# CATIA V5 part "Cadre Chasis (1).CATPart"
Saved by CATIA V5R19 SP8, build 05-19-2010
Part number: Cadre Chasis (1)
Nomenclature: 1
Material "Acier": density 7860 kg/m3, Young's modulus 2e+11 Pa, Poisson ratio 0.266, thermal expansion 1.17e-05 1/K
Bounding box of the stored display mesh (mm): x -290 to 290, y 0 to 780, z -38 to 20
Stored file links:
  C:\Users\rphgr\Desktop\0_Tapis_TC520B_vitesse\Cadre Chasis (1).CATPart
  C:\Program Files (x86)\Dassault Systemes\B19\intel_a\reffiles\standard\MetricThickPitch.txt
  D:\Programmes\DassaultSysteme\win_b64\startup\materials\French\Catalog.CATMaterial
  D:\Documents\1_Travail\1 - ac-limoges.fr\ac-limoges.fr\Emmanuel Maynard - STI2D_Turgot\3 - Supports\Tapis de course TC520B\Tapis de course TC520B_Ca\0_Tapis_TC520B.CATProduct
  C:\Users\rphgr\Desktop\0_Tapis_TC520B_vitesse\Patin (54).CATPart
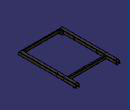
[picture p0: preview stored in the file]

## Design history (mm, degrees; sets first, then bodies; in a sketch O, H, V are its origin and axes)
AxisSystem1: origin (0, 0, 0), X (1, 0, 0), Y (0, 1, 0), Z (0, 0, 1)
Set1
  DatumSurface1: linked copy from another document
Set2
  Sketch1 on YZ plane of AxisSystem1, origin (0, 0, 0), H (0, 1, 0), V (0, 0, 1)
    line L1 (-54.6095, -38) -> (1600.6954, -38)
    reference intersected line E1 through (0, -38) direction (1, 0) from face of DatumSurface1
    coincidence: L1 E1
Body1 "Tube logitudinal" (main body)
  Sketch2 on zx-plane, origin (0, 0, 0), H (1, 0, 0), V (0, 0, -1)
    point P1 (-270, 0)
    line L1 (-250, 17) -> (-250, -17)
    line L2 (-253, -20) -> (-287, -20)
    line L3 (-290, -17) -> (-290, 17)
    line L4 (-287, 20) -> (-253, 20)
    arc A1 centre (-287, 17) radius 3 from (-290, 17) to (-287, 20) cw
    arc A2 centre (-253, 17) radius 3 from (-250, 17) to (-253, 20) ccw
    arc A3 centre (-253, -17) radius 3 from (-250, -17) to (-253, -20) cw
    arc A4 centre (-287, -17) radius 3 from (-287, -20) to (-290, -17) cw
    distance P1 V = 270
    radius A1 = 3
    radius A2 = 3
    radius A3 = 3
    radius A4 = 3
    distance L3 L1 = 40
    distance L4 L2 = 40
    coincidence: P1 H
    vertical: L1 V, L3 V
    horizontal: L2 H, L4 H
    equidistance: L1 L3 P1, L2 L4 P1
    tangency: A1 L3, A1 L4, A2 L1, A2 L4, A3 L1, A3 L2, A4 L2, A4 L3
  Pad1: profile Sketch2, direction (0, 1, 0), length 780, thin wall 1.7
  Sketch3 on face of Pad1, origin (-250, 0, 0), H (0, 1, 0), V (0, 0, 1)
    line L1 (0, -20) -> (10.718, 20)
    point P1 (0, -20)
    reference intersected line E1 (0, -20) -> (0, 20) from start face of Pad1
    line L2 (780, -20) -> (769.282, 20)
    point P3 (780, -20)
    reference intersected line E2 (780, 20) -> (780, -20) from end face of Pad1
    line L3 (10.718, 20) -> (769.282, 20)
    line L4 (780, -20) -> (0, -20)
    reference intersected line E3 through (0, 20) direction (1, 0) from face of Pad1
    reference intersected line E4 through (0, -20) direction (-1, 0) from face of Pad1
    reference intersected line E5 (0, -17) -> (0, 17) from start face of Pad1
    reference intersected line E6 (780, 17) -> (780, -17) from end face of Pad1
    angle L1 E1 = 15
    angle E2 L2 = 15
    horizontal: L3 H, L4 H
    coincidence: L3 E3, L4 E4, P1 E5, P3 E6
  Pocket1: profile Sketch3, direction (-1, 0, 0), through (limit type 3), outer side
  Sketch4 on face of Pad1, origin (0, 0, -20), H (1, 0, 0), V (0, -1, 0)
    point P1 (-270, -780)
    line L1 (-256.6806, -745) -> (-256.6806, -818)
    line L2 (-256.6806, -818) -> (-283.3194, -818)
    line L3 (-283.3194, -818) -> (-283.3194, -745)
    line L4 (-280.3194, -742) -> (-259.6806, -742)
    reference projected line E1 (-250, -780) -> (-290, -780) from edge [face of Pad1 | face of Pocket1 from Sketch3.L2]
    reference projected line E2 (-250, -780) -> (-290, -780) from edge [face of Pad1 | face of Pocket1 from Sketch3.L2]
    arc A1 centre (-280.3194, -745) radius 3 from (-283.3194, -745) to (-280.3194, -742) cw
    arc A2 centre (-259.6806, -745) radius 3 from (-256.6806, -745) to (-259.6806, -742) ccw
    reference intersected line E3 through (-250, 0) direction (0, -1) from face of Pad1
    length L2 = 26.6389
    distance L4 E2 = 38
    radius A1 = 3
    radius A2 = 3
    distance P1 E3 = 20
    vertical: L1 V, L3 V
    horizontal: L2 H, L4 H
    equidistance: L1 L3 P1, L2 L4 P1
    coincidence: P1 E1
    tangency: A1 L3, A1 L4, A2 L1, A2 L4
  Pocket2: profile Sketch4, direction (0, 0, 1), up to face of Pad1
  Sketch5 on face of Pad1, origin (0, 0, 20), H (1, 0, 0), V (0, 1, 0)
    point P1 (-270, 769.282)
    line L1 (-256.6806, 788.282) -> (-256.6806, 753.282)
    line L2 (-259.6806, 750.282) -> (-280.3194, 750.282)
    line L3 (-283.3194, 753.282) -> (-283.3194, 788.282)
    line L4 (-283.3194, 788.282) -> (-256.6806, 788.282)
    reference intersected line E1 through (-283.3194, 0) direction (0, -1) from face of Pocket2 from Sketch4.L3
    reference intersected line E2 through (-256.6806, 0) direction (0, 1) from face of Pocket2 from Sketch4.L1
    reference intersected line E3 (-253, 769.282) -> (-287, 769.282) from face of Pocket1 from Sketch3.L2
    reference intersected line E4 (-253, 769.282) -> (-287, 769.282) from face of Pocket1 from Sketch3.L2
    arc A1 centre (-280.3194, 753.282) radius 3 from (-280.3194, 750.282) to (-283.3194, 753.282) cw
    arc A2 centre (-259.6806, 753.282) radius 3 from (-256.6806, 753.282) to (-259.6806, 750.282) cw
    distance L2 E4 = 19
    radius A1 = 3
    radius A2 = 3
    vertical: L1 V, L3 V
    horizontal: L2 H, L4 H
    equidistance: L1 L3 P1, L2 L4 P1
    coincidence: L3 E1, L1 E2, P1 E3
    tangency: A1 L2, A1 L3, A2 L1, A2 L2
  Pocket3: profile Sketch5, direction (0, 0, -1), through (limit type 3)
  Sketch6 on face of Pad1, origin (-250, 0, 0), H (0, 1, 0), V (0, 0, 1)
    circle A1 centre (767, -4) radius 4.2
    point P1 (767, -4)
    reference intersected line E1 through (0, -20) direction (-1, 0) from face of Pad1
    reference projected point E2 (780, -20) from edge [face of Pad1 | face of Pocket1 from Sketch3.L2]
    circle A2 centre (607, -4) radius 4.2
    point P2 (607, -4)
    circle A3 centre (507, -4) radius 4.2
    point P3 (507, -4)
    reference intersected line E3 through (0, -20) direction (-1, 0) from face of Pad1
    reference intersected line E4 through (0, -20) direction (-1, 0) from face of Pad1
    radius A1 = 4.2
    distance P1 E1 = 16
    distance P1 E2 H = 13
    radius A3 = 4.2
    radius A2 = 4.2
    distance P2 E3 = 16
    distance P3 E4 = 16
    distance P2 P3 = 100
    distance P2 P1 = 160
  Pocket4: profile Sketch6, direction (-1, 0, 0), through (limit type 3)
  Sketch7 on face of Pad1, origin (-270.9117, 715.1257, -20), H (1, 0, 0), V (0, -1, 0)
    point P1 (0.9117, -14.8743)
    reference intersected line E1 through (20.9117, 0) direction (0, -1) from face of Pad1
    reference projected line E2 (17.9117, -64.8743) -> (-16.0883, -64.8743) from edge [face of Pad1 | face of Pocket1 from Sketch3.L2]
    distance P1 E1 = 20
    distance P1 E2 = 50
  Hole1: placed by Sketch7, at (-270, 730, -20) direction (0, 0, 1), diameter 6.647, depth 2, threaded "M8", thread diameter 8, thread depth 2, pitch 1.25
  Sketch8 on face of Pad1, origin (-269.3296, 31.4158, -20), H (1, 0, 0), V (0, -1, 0)
    point P1 (0, -8.5842)
    reference intersected line E1 through (-20.6704, 0) direction (0, 1) from face of Pad1
    reference projected line E2 (16.3296, 31.4158) -> (-17.6704, 31.4158) from edge [face of Pocket1 from Sketch3.L1 | face of Pad1]
    distance P1 E1 = 20.6704
    distance P1 E2 = 40
  Hole2: placed by Sketch8, at (-269.3296, 40, -20) direction (0, 0, 1), diameter 6.647, depth 20, threaded "M8", thread diameter 8, thread depth 2, pitch 1.25
  Sketch9 on face of Pad1, origin (-269.147, 626.9469, 20), H (1, 0, 0), V (0, 1, 0)
    point P1 (-6.853, -27.6649)
    reference projected line E1 (16.147, 142.3351) -> (-17.853, 142.3351) from edge [face of Pocket1 from Sketch3.L2 | face of Pad1]
    reference intersected line E2 through (-20.853, 0) direction (0, 1) from face of Pad1
    distance E1 P1 = 170
    distance P1 E2 = 14
  Hole3: placed by Sketch9, at (-276, 599.282, 20) direction (0, 0, -1), diameter 6.647, depth 20, threaded "M8", thread diameter 8, thread depth 2, pitch 1.25
  Sketch10 on face of Pad1, origin (-261.6012, 536.6172, 20), H (1, 0, 0), V (0, 1, 0)
    point P1 (-14.3988, -22.3352)
    reference projected point E1 (-14.3988, 62.6648) from axis of face of Hole3
    reference intersected line E2 through (-28.3988, 0) direction (0, 1) from face of Pad1
    distance P1 E1 = 85
    distance P1 E2 = 14
  Hole4: placed by Sketch10, at (-276, 514.282, 20) direction (0, 0, -1), diameter 6.647, depth 20, threaded "M8", thread diameter 8, thread depth 2, pitch 1.25
  Mirror1: of the body so far, about yz-plane
  Sketch11 on face of Pad1, origin (-290, 0, 0), H (0, -1, 0), V (0, 0, 1)
    construction line L1 (-552, 0) -> (-562, 0)
    point P1 (-552, 0)
    line L2 (-552, -11.5034) -> (-562, -11.5034)
    line L3 (-562, 11.5034) -> (-552, 11.5034)
    arc A1 centre (-562, 0) radius 11.5034 from (-562, -11.5034) to (-562, 11.5034) cw
    arc A2 centre (-552, 0) radius 11.5034 from (-552, 11.5034) to (-552, -11.5034) cw
    reference projected point E1 (-507, -4) from axis of face of Pocket4 from Sketch6.A3
    distance L1 L2 = 11.5034
    length L1 = 10
    distance E1 P1 H = 45
    coincidence: P1 H
    horizontal: L1 H
    tangency: A1 L2, A2 L2, A1 L3, A2 L3
  Pocket5: profile Sketch11, direction (1, 0, 0), length 2
  Sketch12 on face of Pad1, origin (-250, 0, 0), H (0, 1, 0), V (0, 0, 1)
    construction line L1 (200, 0) -> (210.54, 0)
    point P1 (200, 0)
    line L2 (200, 5.5) -> (210.54, 5.5)
    line L3 (210.54, -5.5) -> (200, -5.5)
    arc A1 centre (210.54, 0) radius 5.5 from (210.54, 5.5) to (210.54, -5.5) cw
    arc A2 centre (200, 0) radius 5.5 from (200, -5.5) to (200, 5.5) cw
    reference projected point E1 (0, -20) from edge [face of Pocket1 from Sketch3.L1 | face of Pad1]
    distance L1 L2 = 5.5
    length L1 = 10.54
    distance P1 E1 H = 200
    coincidence: P1 H
    horizontal: L1 H
    tangency: A1 L2, A2 L2, A1 L3, A2 L3
  Pocket6: profile Sketch12, direction (-1, 0, 0), length 2
Body2 "Traverses"
  Sketch13 on yz-plane, origin (0, 0, 0), H (0, 1, 0), V (0, 0, 1)
    point P1 (17.218, 0)
    line L1 (23.718, 17) -> (23.718, -17)
    line L2 (20.718, -20) -> (13.718, -20)
    line L3 (10.718, -17) -> (10.718, 17)
    line L4 (13.718, 20) -> (20.718, 20)
    reference intersected line E1 through (0, 20) direction (1, 0) from face of Mirror1
    reference projected point E2 (10.718, 20) from edge [face of Pad1 | face of Pocket1 from Sketch3.L1]
    arc A1 centre (20.718, 17) radius 3 from (23.718, 17) to (20.718, 20) ccw
    arc A2 centre (13.718, 17) radius 3 from (10.718, 17) to (13.718, 20) cw
    arc A3 centre (13.718, -17) radius 3 from (13.718, -20) to (10.718, -17) cw
    arc A4 centre (20.718, -17) radius 3 from (20.718, -20) to (23.718, -17) ccw
    radius A1 = 3
    radius A2 = 3
    radius A3 = 3
    radius A4 = 3
    distance L3 L1 = 13
    coincidence: P1 H, L4 E1, L3 E2
    vertical: L1 V, L3 V
    horizontal: L2 H, L4 H
    equidistance: L1 L3 P1, L2 L4 P1
    tangency: A1 L1, A1 L4, A2 L3, A2 L4, A3 L2, A3 L3, A4 L2, A4 L1
  Pad2: profile Sketch13, direction (1, 0, 0), up to face of Mirror1, opposite side up to face of Pad1, thin wall 1.7
  Sketch14 on yz-plane, origin (0, 0, 0), H (0, 1, 0), V (0, 0, 1)
    point P1 (625.968, 0)
    line L1 (636.218, 17) -> (636.218, -17)
    line L2 (633.218, -20) -> (618.718, -20)
    line L3 (615.718, -17) -> (615.718, 17)
    line L4 (618.718, 20) -> (633.218, 20)
    reference intersected line E1 through (0, 20) direction (1, 0) from face of Pad1
    reference intersected line E2 (23.718, 20) -> (23.718, -20) from face of Pad2
    arc A1 centre (618.718, 17) radius 3 from (615.718, 17) to (618.718, 20) cw
    arc A2 centre (633.218, 17) radius 3 from (636.218, 17) to (633.218, 20) ccw
    arc A3 centre (633.218, -17) radius 3 from (636.218, -17) to (633.218, -20) cw
    arc A4 centre (618.718, -17) radius 3 from (618.718, -20) to (615.718, -17) cw
    distance L3 L1 = 20.5
    distance L3 E2 = 592
    radius A1 = 3
    radius A2 = 3
    radius A3 = 3
    radius A4 = 3
    coincidence: P1 H, L4 E1
    vertical: L1 V, L3 V
    horizontal: L2 H, L4 H
    equidistance: L1 L3 P1, L2 L4 P1
    tangency: A1 L3, A1 L4, A2 L1, A2 L4, A3 L1, A3 L2, A4 L2, A4 L3
  Pad3: profile Sketch14, direction (1, 0, 0), up to face of Mirror1, opposite side up to face of Pad1, thin wall 1.7
Body3 "renfort d'angle"
  Sketch15 on face of Pad1, origin (0, 0, -20), H (1, 0, 0), V (0, -1, 0)
    point P1 (-250, -63.718)
    line L1 (-250, -63.718) -> (-239.5, -63.718)
    arc A1 centre (-239.5, -56.218) radius 7.5 from (-239.5, -63.718) to (-232, -56.218) ccw
    line L2 (-232, -56.218) -> (-232, -23.718)
    point P5 (-232, -23.718)
    reference intersected line E1 through (-250, 0) direction (0, -1) from face of Pad1
    reference intersected line E2 through (-250, 0) direction (0, -1) from face of Pad1
    reference intersected line E3 through (0, -23.718) direction (-1, 0) from face of Pad2
    reference intersected line E4 through (0, -23.718) direction (-1, 0) from face of Pad2
    radius A1 = 7.5
    distance L2 E2 = 18
    distance L1 E3 = 40
    horizontal: L1 H
    tangency: A1 L1, L2 A1
    coincidence: P1 E1, E4 P5
  Pad4: profile Sketch15, direction (0, 0, -1), up to face of Pad2, thin wall 0, second thickness 4
  Sketch16 on face of Pad4, origin (-228, 0, 0), H (0, 1, 0), V (0, 0, 1)
    circle A1 centre (48.718, -2) radius 6.25
    point P1 (48.718, -2)
    reference intersected line E1 (56.218, -20) -> (23.718, -20) from start face of Pad4
    reference intersected line E2 (23.718, 17) -> (23.718, -17) from face of Pad2
    radius A1 = 6.25
    distance P1 E1 = 18
    distance P1 E2 = 25
  Pocket7: profile Sketch16, direction (-1, 0, 0), length 4
  Mirror2: of the body so far, about YZ plane of AxisSystem1
Body4 "Ecrou_soudé H -M8"
  Sketch17 on face of Pad1, origin (-250, 0, 0), H (0, 1, 0), V (0, 0, 1)
    point P1 (507, -4)
    point P2 (505.9206, 3.4275)
    point P3 (500.0279, -1.221)
    point P4 (501.1073, -8.6486)
    point P5 (508.0794, -11.4275)
    point P6 (513.9721, -6.779)
    point P7 (512.8927, 0.6486)
    point P8 (502.9742, 1.1032)
    line L1 (505.9206, 3.4275) -> (500.0279, -1.221)
    line L2 (500.0279, -1.221) -> (501.1073, -8.6486)
    line L3 (501.1073, -8.6486) -> (508.0794, -11.4275)
    line L4 (508.0794, -11.4275) -> (513.9721, -6.779)
    line L5 (513.9721, -6.779) -> (512.8927, 0.6486)
    line L6 (512.8927, 0.6486) -> (505.9206, 3.4275)
    construction line L7 (507, -4) -> (502.9742, 1.1032)
    construction circle A1 centre (507, -4) radius 7.5056
    construction arc A2 centre (513.9721, -6.779) radius 7.5056 from (508.0794, -11.4275) to (512.8927, 0.6486) cw
    construction arc A3 centre (500.0279, -1.221) radius 7.5056 from (501.1073, -8.6486) to (505.9206, 3.4275) ccw
    point P9 (607, -4)
    point P10 (610.7528, 2.5)
    point P11 (603.2472, 2.5)
    point P12 (599.4944, -4)
    point P13 (603.2472, -10.5)
    point P14 (610.7528, -10.5)
    point P15 (614.5056, -4)
    point P16 (607, 2.5)
    line L8 (610.7528, 2.5) -> (603.2472, 2.5)
    line L9 (603.2472, 2.5) -> (599.4944, -4)
    line L10 (599.4944, -4) -> (603.2472, -10.5)
    line L11 (603.2472, -10.5) -> (610.7528, -10.5)
    line L12 (610.7528, -10.5) -> (614.5056, -4)
    line L13 (614.5056, -4) -> (610.7528, 2.5)
    construction line L14 (607, -4) -> (607, 2.5)
    construction circle A4 centre (607, -4) radius 7.5056
    construction arc A5 centre (610.7528, -10.5) radius 7.5056 from (603.2472, -10.5) to (614.5056, -4) cw
    construction arc A6 centre (603.2472, 2.5) radius 7.5056 from (599.4944, -4) to (610.7528, 2.5) ccw
    reference projected point E1 (507, -4) from axis of face of Pocket4 from Sketch6.A3
    reference projected point E2 (607, -4) from axis of face of Pocket4 from Sketch6.A2
    distance L8 L11 = 13
    distance L4 L1 = 13
    coincidence: A1 P2, A1 P3, A1 P4, A1 P5, A1 P6, A1 P7, A2 P1, A3 P1, A4 P10, A4 P11, A4 P12, A4 P13, A4 P14, A4 P15, A5 P9, A6 P9, P1 E1, P9 E2
    midpoint: P8 L1, P16 L8
    vertical: L14 V
  Pad5: profile Sketch17, direction (1, 0, 0), length 6
  Sketch18 on end face of Pad5, origin (-244, 506.8348, -3.7956), H (0, 1, 0), V (0, 0, 1)
    point P1 (0.1652, -0.2044)
    reference projected point E1 (0.1652, -0.2044) from axis of face of Pocket4 from Sketch6.A3
    coincidence: P1 E1
  Hole5: placed by Sketch18, at (-244, 507, -4) direction (-1, 0, 0), diameter 6.647, through (limit type 6), threaded "M8", thread diameter 8, thread depth 6, pitch 1.25
  Sketch19 on end face of Pad5, origin (-244, 606.4855, -3.8888), H (0, 1, 0), V (0, 0, 1)
    point P1 (0.5145, -0.1112)
    reference projected point E1 (0.5145, -0.1112) from axis of face of Pocket4 from Sketch6.A2
    coincidence: E1 P1
  Hole6: placed by Sketch19, at (-244, 607, -4) direction (-1, 0, 0), diameter 6.647, through (limit type 6), threaded "M8", thread diameter 8, thread depth 6, pitch 1.25
  Plane1: type OffsetPt, RefPlane face of Pad5 from Sketch17.L3, RefPoint {point type Center, Curve edge [end face of Pad5 | face of Hole5]}
  Sketch20 on Plane1, origin (0, 68.1356, 170.9231), H (1, 0, 0), V (0, -0.9289, 0.3703)
    line L1 (-245.5, -464.935) -> (-244, -466.435)
    line L2 (-244, -466.435) -> (-244, -464.935)
    line L3 (-244, -464.935) -> (-245.5, -464.935)
    reference intersected line E1 (-244, -468.7104) -> (-244, -476.2159) from end face of Pad5
    reference projected line E2 (-250, -464.935) -> (-244, -464.935) from edge [face of Pad5 from Sketch17.L2 | face of Pad5 from Sketch17.L1]
    length L3 = 1.5
    angle L1 L3 = 45
    vertical: L2 V
    coincidence: L2 E1, L3 E2
  Groove1: profile Sketch20, axis axis of face of Hole5, angle 360
  Plane2: type OffsetPt, RefPlane face of Pad5 from Sketch17.L11, RefPoint {point type Center, Curve edge [end face of Pad5 | face of Hole6]}
  Sketch21 on Plane2, origin (0, 34.5594, -4), H (1, 0, 0), V (0, -1, 0)
    line L1 (-245.5, -564.935) -> (-244, -566.435)
    line L2 (-244, -566.435) -> (-244, -564.935)
    line L3 (-244, -564.935) -> (-245.5, -564.935)
    reference projected line E1 (-250, -564.935) -> (-244, -564.935) from edge [face of Pad5 from Sketch17.L10 | face of Pad5 from Sketch17.L9]
    reference intersected line E2 through (-244, 0) direction (0, 1) from end face of Pad5
    length L3 = 1.5
    angle L1 L3 = 45
    vertical: L2 V
    coincidence: L3 E1, L2 E2
  Groove2: profile Sketch21, axis axis of face of Hole6, angle 360
  Mirror3: of the body so far, about YZ plane of AxisSystem1
Body5 "Ecrou soudé H-M10"
  Sketch22 on face of Pad4, origin (-232, 0, 0), H (0, -1, 0), V (0, 0, 1)
    point P1 (-48.718, -2)
    point P2 (-39.9347, 2.3803)
    point P3 (-48.1198, 7.7967)
    point P4 (-56.9031, 3.4164)
    point P5 (-57.5013, -6.3803)
    point P6 (-49.3162, -11.7967)
    point P7 (-40.5329, -7.4164)
    point P8 (-44.0272, 5.0885)
    line L1 (-39.9347, 2.3803) -> (-48.1198, 7.7967)
    line L2 (-48.1198, 7.7967) -> (-56.9031, 3.4164)
    line L3 (-56.9031, 3.4164) -> (-57.5013, -6.3803)
    line L4 (-57.5013, -6.3803) -> (-49.3162, -11.7967)
    line L5 (-49.3162, -11.7967) -> (-40.5329, -7.4164)
    line L6 (-40.5329, -7.4164) -> (-39.9347, 2.3803)
    construction line L7 (-48.718, -2) -> (-44.0272, 5.0885)
    construction circle A1 centre (-48.718, -2) radius 9.815
    construction arc A2 centre (-49.3162, -11.7967) radius 9.815 from (-57.5013, -6.3803) to (-40.5329, -7.4164) cw
    construction arc A3 centre (-48.1198, 7.7967) radius 9.815 from (-56.9031, 3.4164) to (-39.9347, 2.3803) ccw
    reference projected point E1 (-48.718, -2) from axis of face of Pocket7 from Sketch16.A1
    distance L1 L4 = 17
    coincidence: A1 P2, A1 P3, A1 P4, A1 P5, A1 P6, A1 P7, A2 P1, A3 P1, P1 E1
    midpoint: P8 L1
  Pad6: profile Sketch22, direction (-1, 0, 0), length 7
  Sketch23 on end face of Pad6, origin (-239, 48.2951, -3.9398), H (0, 1, 0), V (0, 0, -1)
    point P1 (0.4229, -1.9398)
    reference projected circle E1 centre (0.4229, -1.9398) radius 6.25 from edge [face of Pad4 | face of Pocket7 from Sketch16.A1]
    concentricity: P1 E1
  Hole7: placed by Sketch23, at (-239, 48.718, -2) direction (1, 0, 0), diameter 8.376, through (limit type 6), threaded "M10", thread diameter 10, thread depth 6, pitch 1.5
  Plane3: type OffsetPt, RefPlane face of Pad6 from Sketch22.L5, RefPoint {point type Center, Curve edge [end face of Pad6 | face of Hole7]}
  Sketch24 on Plane3, origin (0, 8.9046, 17.8553), H (-1, 0, 0), V (0, -0.8949, 0.4463)
    line L1 (237.5, -34.6748) -> (239, -34.6748)
    line L2 (239, -34.6748) -> (239, -36.1748)
    line L3 (239, -36.1748) -> (237.5, -34.6748)
    reference intersected line E1 (239, -34.6748) -> (239, -54.3047) from end face of Pad6
    reference projected line E2 (232, -34.6748) -> (239, -34.6748) from edge [face of Pad6 from Sketch22.L1 | face of Pad6 from Sketch22.L6]
    angle L3 L1 = 45
    length L1 = 1.5
    horizontal: L1 H
    vertical: L2 V
    coincidence: L2 E1, L1 E2
  Groove3: profile Sketch24, axis axis of face of Hole7, angle 360
  Mirror4: of the body so far, about YZ plane of AxisSystem1
Body6 "Chappe Vérin"
  Sketch25 on face of Pad3, origin (0, 0, -20), H (1, 0, 0), V (0, 1, 0)
    point P1 (-9.5, 588.718)
    line L1 (-9.5, 588.718) -> (-9.5, 612.718)
    line L2 (-6.5, 615.718) -> (6.5, 615.718)
    line L3 (9.5, 612.718) -> (9.5, 588.718)
    point P2 (9.5, 588.718)
    reference intersected line E1 through (0, 0) direction (0, 1) from YZ plane of AxisSystem1
    reference intersected line E2 through (0, 615.718) direction (-1, 0) from face of Pad3
    arc A1 centre (-6.5, 612.718) radius 3 from (-9.5, 612.718) to (-6.5, 615.718) cw
    arc A2 centre (6.5, 612.718) radius 3 from (6.5, 615.718) to (9.5, 612.718) cw
    distance L1 L3 = 19
    distance L3 E1 = 9.5
    radius A1 = 3
    radius A2 = 3
    distance P2 L2 = 27
    distance L2 P1 = 27
    vertical: L1 V, L3 V
    horizontal: L2 H
    coincidence: L2 E2
    tangency: A1 L1, A1 L2, A2 L2, A2 L3
  Pad7: profile Sketch25, direction (0, 0, 1), length 22, thin wall 2.5
  Fillet1: radius 11, on edge [start face of Pad7 | face of Pad7] (x2); edge [face of Pad7 | end face of Pad7] (x2)
  Sketch26 on face of Pad7, origin (-9.5, 0, 0), H (0, -1, 0), V (0, 0, 1)
    circle A1 centre (-599.718, -9) radius 4.2
    reference projected point E1 (-599.718, -9) from axis of face of Fillet1
    radius A1 = 4.2
    concentricity: A1 E1
  Pocket8: profile Sketch26, direction (1, 0, 0), through (limit type 3)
